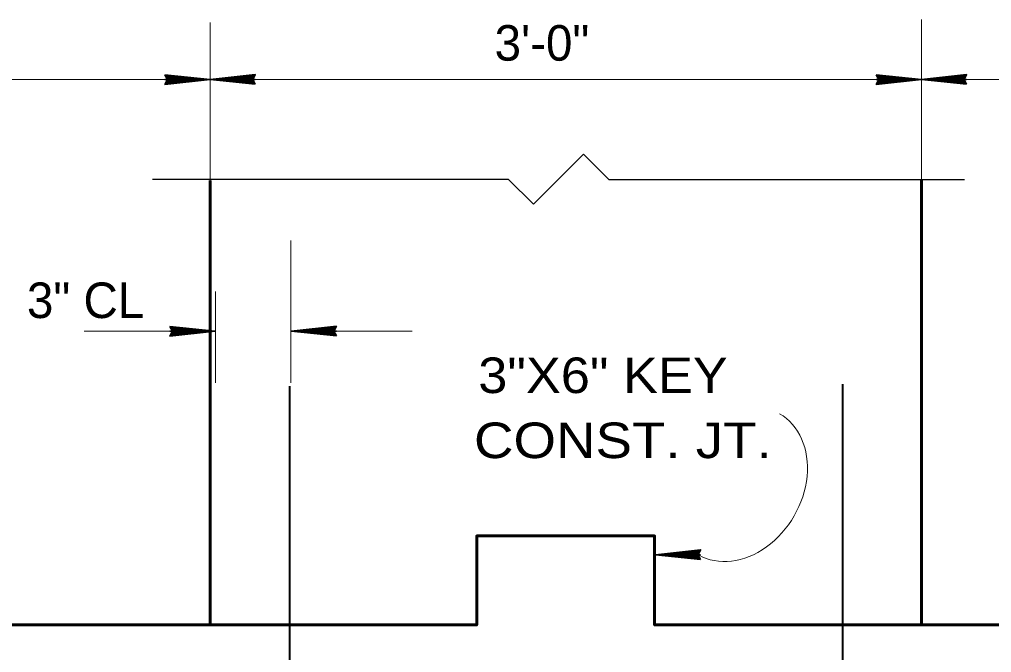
# Model space of a CAD drawing. Extents: x 4.49 to 7.69, y 0.28 to 2.27.
# Drawn here: x 6.4715 to 6.6993, y 1.9491 to 2.0975 of the extents above; entities that cross this region are included whole.
import ezdxf

# ---------------------------------------------------------------- set-up
doc = ezdxf.new("R2010")
doc.units = 0
doc.header["$LTSCALE"] = 0.0033
doc.layers.add('1', color=7, linetype='Continuous', lineweight=35)

msp = doc.modelspace()

# ---------------------------------------------------------------- linework, layer by layer
at = {"layer": '1', "lineweight": 13}
for p, q in [((6.516167, 2.05975), (6.516167, 2.09675)), ((6.682833, 2.05975), (6.682833, 2.0975)), ((6.35025, 2.083417), (6.848917, 2.083417)), ((6.535083, 2.012333), (6.535083, 2.045667)), ((6.517417, 2.012333), (6.517417, 2.03375)), ((6.486667, 2.024417), (6.5075, 2.024417)), ((6.544917, 2.024417), (6.5635, 2.024417))]:
    msp.add_line(p, q, dxfattribs=at)
at = {"layer": '1'}
for p, q in [((6.505833, 2.084417), (6.513667, 2.0835)), ((6.505833, 2.084417), (6.513667, 2.0835)), ((6.505833, 2.084333), (6.513667, 2.0835)), ((6.505833, 2.08425), (6.513667, 2.083417)), ((6.505833, 2.08425), (6.513667, 2.08325)), ((6.5265, 2.0845), (6.519167, 2.083667)), ((6.5265, 2.084333), (6.519167, 2.083583)), ((6.5265, 2.08425), (6.519167, 2.083417)), ((6.6725, 2.084417), (6.680333, 2.0835)), ((6.6725, 2.084417), (6.680333, 2.0835)), ((6.6725, 2.084333), (6.680333, 2.0835)), ((6.6725, 2.08425), (6.680333, 2.083417)), ((6.6725, 2.08425), (6.680333, 2.08325)), ((6.693167, 2.0845), (6.685833, 2.083667)), ((6.693167, 2.084333), (6.685833, 2.083583)), ((6.693167, 2.08425), (6.685833, 2.083417)), ((6.505583, 2.083417), (6.516167, 2.083417)), ((6.50575, 2.08275), (6.513083, 2.0835)), ((6.505833, 2.082583), (6.513167, 2.083417)), ((6.505833, 2.0825), (6.513167, 2.08325)), ((6.505833, 2.082333), (6.513167, 2.083167)), ((6.52675, 2.083417), (6.516167, 2.083417)), ((6.5265, 2.082583), (6.518667, 2.083583)), ((6.5265, 2.082583), (6.518667, 2.083417)), ((6.5265, 2.082417), (6.518667, 2.083333)), ((6.5265, 2.082417), (6.518667, 2.083333)), ((6.5265, 2.0825), (6.518667, 2.083333)), ((6.526583, 2.084083), (6.51925, 2.083333)), ((6.67225, 2.083417), (6.682833, 2.083417)), ((6.672417, 2.08275), (6.67975, 2.0835)), ((6.6725, 2.082583), (6.679833, 2.083417)), ((6.6725, 2.0825), (6.679833, 2.08325)), ((6.6725, 2.082333), (6.679833, 2.083167)), ((6.693417, 2.083417), (6.682833, 2.083417)), ((6.693167, 2.082583), (6.685333, 2.083583)), ((6.693167, 2.082583), (6.685333, 2.083417)), ((6.693167, 2.082417), (6.685333, 2.083333)), ((6.693167, 2.082417), (6.685333, 2.083333)), ((6.693167, 2.0825), (6.685333, 2.083333)), ((6.69325, 2.084083), (6.685917, 2.083333)), ((6.507, 2.025417), (6.514833, 2.0245)), ((6.507, 2.025417), (6.514833, 2.0245)), ((6.507, 2.025333), (6.514833, 2.0245)), ((6.507, 2.02525), (6.514833, 2.024417)), ((6.507, 2.02525), (6.514833, 2.02425)), ((6.5455, 2.0255), (6.538167, 2.024667)), ((6.5455, 2.025333), (6.538167, 2.024583)), ((6.5455, 2.02525), (6.538167, 2.024417)), ((6.545583, 2.025083), (6.53825, 2.024333)), ((6.50675, 2.024417), (6.517333, 2.024417)), ((6.506917, 2.02375), (6.51425, 2.0245)), ((6.507, 2.023583), (6.514333, 2.024417)), ((6.507, 2.0235), (6.514333, 2.02425)), ((6.507, 2.023333), (6.514333, 2.024167)), ((6.54575, 2.024417), (6.535167, 2.024417)), ((6.5455, 2.023583), (6.537667, 2.024583)), ((6.5455, 2.023583), (6.537667, 2.024417)), ((6.5455, 2.023417), (6.537667, 2.024333)), ((6.5455, 2.023417), (6.537667, 2.024333)), ((6.5455, 2.0235), (6.537667, 2.024333)), ((6.630833, 1.973083), (6.6235, 1.97225)), ((6.630833, 1.972917), (6.6235, 1.972167)), ((6.630833, 1.972833), (6.6235, 1.972)), ((6.630917, 1.972667), (6.623583, 1.971917)), ((6.631083, 1.972), (6.6205, 1.972)), ((6.630833, 1.971167), (6.623, 1.972167)), ((6.630833, 1.971167), (6.623, 1.972)), ((6.630833, 1.971), (6.623, 1.971917)), ((6.630833, 1.971), (6.623, 1.971917)), ((6.630833, 1.971083), (6.623, 1.971917))]:
    msp.add_line(p, q, dxfattribs=at)
for points in [[(6.505583, 2.0845), (6.516167, 2.083417), (6.505583, 2.08225), (6.506167, 2.083417)], [(6.52675, 2.082333), (6.516167, 2.083417), (6.52675, 2.084583), (6.526167, 2.083417)], [(6.67225, 2.0845), (6.682833, 2.083417), (6.67225, 2.08225), (6.672833, 2.083417)], [(6.693417, 2.082333), (6.682833, 2.083417), (6.693417, 2.084583), (6.692833, 2.083417)], [(6.506333, 2.0835), (6.511, 2.083583), (6.511, 2.0835), (6.510083, 2.0835), (6.506333, 2.083583), (6.509333, 2.083667), (6.506167, 2.08375), (6.508417, 2.083833), (6.506167, 2.083917), (6.509667, 2.083667), (6.514333, 2.0835), (6.513417, 2.08325), (6.514667, 2.08325), (6.506333, 2.08325), (6.50875, 2.083083), (6.506167, 2.083083), (6.5115, 2.0835), (6.506167, 2.082833)], [(6.526, 2.083333), (6.521333, 2.08325), (6.521333, 2.083333), (6.52225, 2.083333), (6.526, 2.08325), (6.523, 2.083167), (6.526167, 2.083083), (6.523917, 2.083), (6.526167, 2.082917), (6.522667, 2.083167), (6.518, 2.083333), (6.518917, 2.083583), (6.517667, 2.083583), (6.526, 2.083583), (6.523583, 2.08375), (6.526167, 2.08375), (6.520833, 2.083333), (6.526167, 2.084)], [(6.673, 2.0835), (6.677667, 2.083583), (6.677667, 2.0835), (6.67675, 2.0835), (6.673, 2.083583), (6.676, 2.083667), (6.672833, 2.08375), (6.675083, 2.083833), (6.672833, 2.083917), (6.676333, 2.083667), (6.681, 2.0835), (6.680083, 2.08325), (6.681333, 2.08325), (6.673, 2.08325), (6.675417, 2.083083), (6.672833, 2.083083), (6.678167, 2.0835), (6.672833, 2.082833)], [(6.692667, 2.083333), (6.688, 2.08325), (6.688, 2.083333), (6.688917, 2.083333), (6.692667, 2.08325), (6.689667, 2.083167), (6.692833, 2.083083), (6.690583, 2.083), (6.692833, 2.082917), (6.689333, 2.083167), (6.684667, 2.083333), (6.685583, 2.083583), (6.684333, 2.083583), (6.692667, 2.083583), (6.69025, 2.08375), (6.692833, 2.08375), (6.6875, 2.083333), (6.692833, 2.084)], [(6.50675, 2.0255), (6.517333, 2.024417), (6.50675, 2.02325), (6.507333, 2.024417)], [(6.54575, 2.023333), (6.535167, 2.024417), (6.54575, 2.025583), (6.545167, 2.024417)], [(6.545, 2.024333), (6.540333, 2.02425), (6.540333, 2.024333), (6.54125, 2.024333), (6.545, 2.02425), (6.542, 2.024167), (6.545167, 2.024083), (6.542917, 2.024), (6.545167, 2.023917), (6.541667, 2.024167), (6.537, 2.024333), (6.537917, 2.024583), (6.536667, 2.024583), (6.545, 2.024583), (6.542583, 2.02475), (6.545167, 2.02475), (6.539833, 2.024333), (6.545167, 2.025)], [(6.5075, 2.0245), (6.512167, 2.024583), (6.512167, 2.0245), (6.51125, 2.0245), (6.5075, 2.024583), (6.5105, 2.024667), (6.507333, 2.02475), (6.509583, 2.024833), (6.507333, 2.024917), (6.510833, 2.024667), (6.5155, 2.0245), (6.514583, 2.02425), (6.515833, 2.02425), (6.5075, 2.02425), (6.509917, 2.024083), (6.507333, 2.024083), (6.512667, 2.0245), (6.507333, 2.023833)], [(6.631083, 1.970917), (6.6205, 1.972), (6.631083, 1.973167), (6.6305, 1.972)], [(6.630333, 1.971917), (6.625667, 1.971833), (6.625667, 1.971917), (6.626583, 1.971917), (6.630333, 1.971833), (6.627333, 1.97175), (6.6305, 1.971667), (6.62825, 1.971583), (6.6305, 1.9715), (6.627, 1.97175), (6.622333, 1.971917), (6.62325, 1.972167), (6.622, 1.972167), (6.630333, 1.972167), (6.627917, 1.972333), (6.6305, 1.972333), (6.625167, 1.971917), (6.6305, 1.972583)]]:
    msp.add_lwpolyline(points, close=True, dxfattribs=at)
for points in [[(6.506333, 2.0835), (6.505917, 2.08425), (6.506167, 2.084), (6.506333, 2.083667), (6.506583, 2.08375), (6.506417, 2.084083), (6.50625, 2.083333), (6.506083, 2.082833), (6.505833, 2.082417)], [(6.526, 2.083333), (6.526417, 2.082583), (6.526167, 2.082833), (6.526, 2.083167), (6.52575, 2.083083), (6.525917, 2.08275), (6.526083, 2.0835), (6.52625, 2.084), (6.5265, 2.084417)], [(6.673, 2.0835), (6.672583, 2.08425), (6.672833, 2.084), (6.673, 2.083667), (6.67325, 2.08375), (6.673083, 2.084083), (6.672917, 2.083333), (6.67275, 2.082833), (6.6725, 2.082417)], [(6.692667, 2.083333), (6.693083, 2.082583), (6.692833, 2.082833), (6.692667, 2.083167), (6.692417, 2.083083), (6.692583, 2.08275), (6.69275, 2.0835), (6.692917, 2.084), (6.693167, 2.084417)], [(6.5075, 2.0245), (6.507083, 2.02525), (6.507333, 2.025), (6.5075, 2.024667), (6.50775, 2.02475), (6.507583, 2.025083), (6.507417, 2.024333), (6.50725, 2.023833), (6.507, 2.023417)], [(6.545, 2.024333), (6.545417, 2.023583), (6.545167, 2.023833), (6.545, 2.024167), (6.54475, 2.024083), (6.544917, 2.02375), (6.545083, 2.0245), (6.54525, 2.025), (6.5455, 2.025417)], [(6.630333, 1.971917), (6.63075, 1.971167), (6.6305, 1.971417), (6.630333, 1.97175), (6.630083, 1.971667), (6.63025, 1.971333), (6.630417, 1.972083), (6.630583, 1.972583), (6.630833, 1.973)]]:
    msp.add_lwpolyline(points, dxfattribs=at)
at = {"layer": '1', "lineweight": 25}
msp.add_lwpolyline([(6.502667, 2.060083), (6.586, 2.060083), (6.591917, 2.054167), (6.603667, 2.065917), (6.609583, 2.06), (6.692917, 2.06)], dxfattribs=at)
at = {"layer": '1', "lineweight": 60}
for points in [[(6.3495, 1.955583), (6.516167, 1.955583), (6.516167, 2.05975)], [(6.682833, 2.05975), (6.682833, 1.955583), (6.8495, 1.955583)], [(6.516167, 1.955583), (6.578667, 1.955583), (6.578667, 1.976417), (6.620333, 1.976417), (6.620333, 1.955583), (6.682833, 1.955583)]]:
    msp.add_lwpolyline(points, dxfattribs=at)
at = {"layer": '1', "lineweight": 40}
for points in [[(6.472333, 1.899333), (6.534833, 1.899333), (6.534833, 2.0115)], [(6.664333, 2.012), (6.664333, 1.899), (6.726833, 1.899)]]:
    msp.add_lwpolyline(points, dxfattribs=at)
at = {"layer": '1', "lineweight": 13}
msp.add_ellipse((6.640083, 1.988542), major_axis=(-0.0095, -0.016542), ratio=0.782092, start_param=6.2831853, end_param=9.424778, dxfattribs=at)

# ---------------------------------------------------------------- texts
at = {"layer": '1'}
for s, height, p in [('3\'-0"', 0.008333, (6.582833, 2.087833)), ('3" CL', 0.008334, (6.47325, 2.0275))]:
    msp.add_text(s, height=height, dxfattribs=at).set_placement(p)
for s, width, p in [('3"X6" KEY', 1.1, (6.579, 2.009917)), ('CONST. JT. ', 1.15, (6.578, 1.994667))]:
    msp.add_text(s, height=0.008334, dxfattribs=dict(at, width=width)).set_placement(p)

doc.saveas('drawing.dxf')
